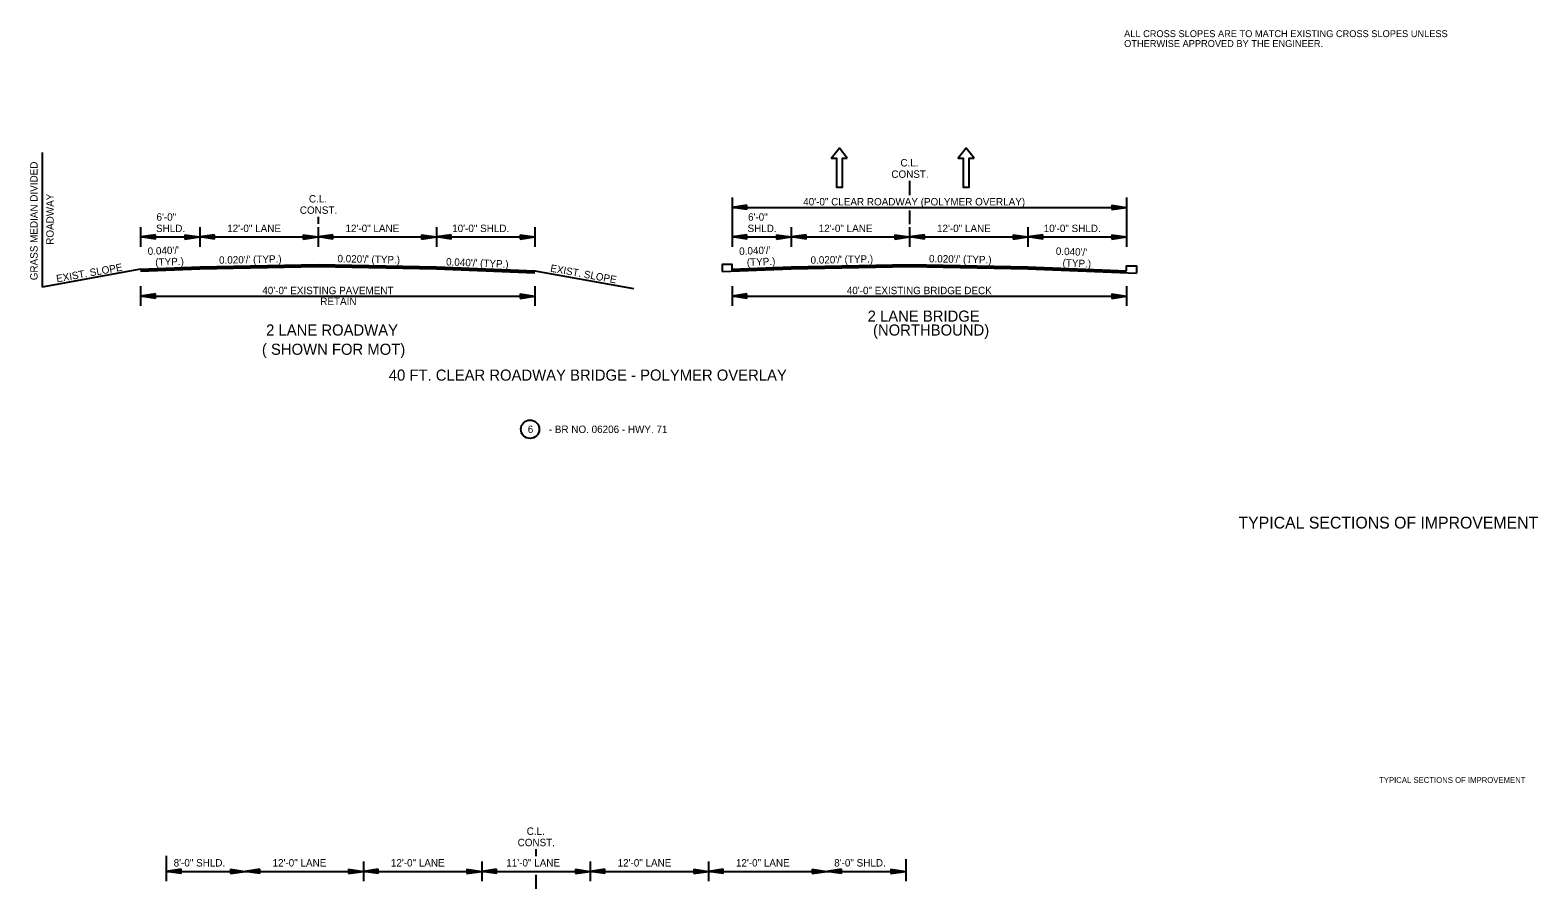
# Model space of a CAD drawing. Extents: x 550980 to 1930787, y -1972975 to 596640.
# Drawn here: x 551017 to 552546, y -1947048 to -1946177 of the extents above; entities that cross this region are included whole.
import ezdxf

# ---------------------------------------------------------------- set-up
doc = ezdxf.new("R2010")
doc.units = 0
for name, color, linetype in [('R_Border', 7, 'Continuous'), ('R_Border Notes', 7, 'Continuous'), ('R_Draft', 7, 'Continuous'), ('S_AREA_CALC', 7, 'Continuous')]:
    doc.layers.add(name, color=color, linetype=linetype)

# ---------------------------------------------------------------- blocks, each defined once
blk = doc.blocks.new('BPPOLY')
at = {"layer": 'R_Border'}
blk.add_circle((0, 0), 9.34, dxfattribs=at)
blk = doc.blocks.new('ARROW')
at = {"layer": 'R_Draft'}
for p, q in [((-2, 0.3), (0, 0)), ((-2, 0.3), (-2, -0.3)), ((-2, 0.25), (-0.334, 0)), ((-2, 0.199), (-0.678, 0)), ((-2, 0.149), (-1.011, 0)), ((-2, 0.097), (-1.35, 0)), ((-2, 0.047), (-1.684, 0)), ((-2, -0.3), (0, 0)), ((-2, -0.098), (-1.35, 0)), ((-2, -0.199), (-0.678, 0)), ((-2, -0.25), (-0.334, 0)), ((-2, -0.149), (-1.011, 0)), ((-2, -0.047), (-1.684, 0))]:
    blk.add_line(p, q, dxfattribs=at)

msp = doc.modelspace()

# ---------------------------------------------------------------- linework, layer by layer
at = {"layer": 'R_Border'}
for p, q in [((551028.7, -1946300.8), (551028.7, -1946437.2)), ((551908.7, -1946329.4), (551908.7, -1946343.9)), ((551728.7, -1946346.4), (551728.7, -1946396.4)), ((552128.7, -1946346.4), (552128.7, -1946396.4)), ((551728.7, -1946356.4), (552128.7, -1946356.4)), ((551908.7, -1946359.4), (551908.7, -1946373.4)), ((551128.7, -1946376.4), (551128.7, -1946396.4)), ((551188.7, -1946376.4), (551188.7, -1946396.4)), ((551308.7, -1946365.9), (551308.7, -1946373.2)), ((551308.7, -1946376.4), (551308.7, -1946396.4)), ((551428.7, -1946376.4), (551428.7, -1946396.4)), ((551528.7, -1946376.4), (551528.7, -1946396.4)), ((551788.7, -1946376.4), (551788.7, -1946396.4)), ((551908.7, -1946376.4), (551908.7, -1946396.4)), ((552028.7, -1946376.4), (552028.7, -1946396.4)), ((551128.7, -1946386.4), (551528.7, -1946386.4)), ((551728.7, -1946386.4), (552128.7, -1946386.4)), ((551128.7, -1946419.2), (551028.7, -1946437.2)), ((551528.7, -1946420.8), (551628.7, -1946438.8)), ((551128.7, -1946436.4), (551128.7, -1946456.4)), ((551528.7, -1946436.4), (551528.7, -1946456.4)), ((551728.7, -1946436.4), (551728.7, -1946456.4)), ((552128.7, -1946436.4), (552128.7, -1946456.4)), ((551128.7, -1946446.4), (551528.7, -1946446.4)), ((551728.7, -1946446.4), (552128.7, -1946446.4)), ((551154.7, -1947014), (551154.7, -1947039.9)), ((551529.7, -1947007.3), (551529.7, -1947014.5)), ((551904.7, -1947017.4), (551904.7, -1947039.9)), ((551154.7, -1947029.9), (551904.7, -1947029.9)), ((551354.7, -1947019.9), (551354.7, -1947039.9)), ((551474.7, -1947019.9), (551474.7, -1947039.9)), ((551529.7, -1947033.5), (551529.7, -1947047.5)), ((551584.7, -1947019.9), (551584.7, -1947039.9)), ((551704.7, -1947019.9), (551704.7, -1947039.9))]:
    msp.add_line(p, q, dxfattribs=at)
for points in [[(551845.5, -1946306.6), (551837.5, -1946296.2), (551829.5, -1946306.6), (551834.5, -1946306.6), (551834.5, -1946336), (551840.5, -1946336), (551840.5, -1946306.6)], [(551974.1, -1946306.6), (551966.1, -1946296.2), (551958.1, -1946306.6), (551963.1, -1946306.6), (551963.1, -1946336), (551969.1, -1946336), (551969.1, -1946306.6)]]:
    msp.add_lwpolyline(points, close=True, dxfattribs=at)
for points in [[(551128.7, -1946419.2), (551188.7, -1946416.8), (551308.7, -1946414.4), (551428.7, -1946416.8), (551528.7, -1946420.8)], [(551128.7, -1946419.5), (551188.7, -1946417.1), (551308.7, -1946414.7), (551428.7, -1946417.1), (551528.7, -1946421.1)], [(551128.7, -1946419.8), (551188.7, -1946417.4), (551308.7, -1946415), (551428.7, -1946417.4), (551528.7, -1946421.4)], [(551128.7, -1946420.1), (551188.7, -1946417.7), (551308.7, -1946415.3), (551428.7, -1946417.7), (551528.7, -1946421.7)], [(551128.7, -1946420.4), (551188.7, -1946418), (551308.7, -1946415.6), (551428.7, -1946418), (551528.7, -1946422)], [(551128.7, -1946420.7), (551188.7, -1946418.3), (551308.7, -1946415.9), (551428.7, -1946418.3), (551528.7, -1946422.3)], [(551128.7, -1946421), (551188.7, -1946418.6), (551308.7, -1946416.2), (551428.7, -1946418.6), (551528.7, -1946422.6)], [(551728.7, -1946420.7), (551728.7, -1946414.2), (551718.7, -1946414.2), (551718.7, -1946421.4)], [(551718.7, -1946421.4), (551788.7, -1946418.6), (551908.7, -1946416.2), (552028.7, -1946418.6), (552138.7, -1946423)], [(551728.7, -1946419.2), (551788.7, -1946416.8), (551908.7, -1946414.4), (552028.7, -1946416.8), (552128.7, -1946420.8)], [(551728.7, -1946419.5), (551788.7, -1946417.1), (551908.7, -1946414.7), (552028.7, -1946417.1), (552128.7, -1946421.1)], [(551728.7, -1946419.8), (551788.7, -1946417.4), (551908.7, -1946415), (552028.7, -1946417.4), (552128.7, -1946421.4)], [(551728.7, -1946420.1), (551788.7, -1946417.7), (551908.7, -1946415.3), (552028.7, -1946417.7), (552128.7, -1946421.7)], [(551728.7, -1946420.4), (551788.7, -1946418), (551908.7, -1946415.6), (552028.7, -1946418), (552128.7, -1946422)], [(551728.7, -1946420.7), (551788.7, -1946418.3), (551908.7, -1946415.9), (552028.7, -1946418.3), (552128.7, -1946422.3)], [(552128.7, -1946420.8), (552128.7, -1946415.8), (552138.7, -1946415.8), (552138.7, -1946423)]]:
    msp.add_lwpolyline(points, dxfattribs=at)

# ---------------------------------------------------------------- block references
at = {"layer": 'R_Border', "xscale": 7.5, "yscale": 7.5, "rotation": 180}
for p in [(551728.7, -1946356.4), (551128.7, -1946386.4), (551188.7, -1946386.4), (551308.7, -1946386.4), (551428.7, -1946386.4), (551728.7, -1946386.4), (551788.7, -1946386.4), (551908.7, -1946386.4), (552028.7, -1946386.4), (551128.7, -1946446.4), (551728.7, -1946446.4), (551154.7, -1947029.9), (551234.7, -1947029.9), (551354.7, -1947029.9), (551474.7, -1947029.9), (551584.7, -1947029.9), (551704.7, -1947029.9), (551824.7, -1947029.9)]:
    msp.add_blockref('ARROW', p, dxfattribs=at)
at = {"layer": 'R_Border', "xscale": 7.5, "yscale": 7.5}
for p in [(552128.7, -1946356.4), (551188.7, -1946386.4), (551308.7, -1946386.4), (551428.7, -1946386.4), (551528.7, -1946386.4), (551788.7, -1946386.4), (551908.7, -1946386.4), (552028.7, -1946386.4), (552128.7, -1946386.4), (551528.7, -1946446.4), (552128.7, -1946446.4), (551234.7, -1947029.9), (551354.7, -1947029.9), (551474.7, -1947029.9), (551584.7, -1947029.9), (551704.7, -1947029.9), (551824.7, -1947029.9), (551904.7, -1947029.9)]:
    msp.add_blockref('ARROW', p, dxfattribs=at)
at = {"layer": 'R_Border'}
msp.add_blockref('BPPOLY', (551523.7, -1946581.4), dxfattribs=at)

# ---------------------------------------------------------------- texts
for s, height, rotation, p in [('GRASS MEDIAN DIVIDED', 7.5, 90, (551024.2, -1946430.3)), ('ROADWAY', 7.5, 90, (551040.5, -1946394.3)), ("0.040'/'", 7.5, 2.2916, (551136, -1946404.6)), ('(TYP.)', 7.5, 2.2916, (551143.7, -1946415.8)), ("0.020'/' (TYP.)", 7.5, 1.1458, (551208.3, -1946413.6)), ("0.020'/' (TYP.)", 7.5, 358.8542, (551328.3, -1946412)), ("0.040'/' (TYP.)", 7.5, 357.7084, (551438.4, -1946415.2)), ("0.040'/'", 7.5, 2.2916, (551736, -1946404.6)), ('(TYP.)', 7.5, 2.2916, (551743.7, -1946415.8)), ("0.020'/' (TYP.)", 7.5, 1.1458, (551808.3, -1946413.6)), ("0.020'/' (TYP.)", 7.5, 358.8542, (551928.3, -1946412)), ("0.040'/'", 7.5, 357.7084, (552056.9, -1946404.4)), ('EXIST. SLOPE', 7.5, 10.204, (551043.8, -1946432.5)), ('EXIST. SLOPE', 7.5, 349.796, (551543.8, -1946421.5)), ('(TYP.)', 7.5, 357.7084, (552063.7, -1946416.2)), ('TYPICAL SECTIONS OF IMPROVEMENT', 12, 360, (552242.3, -1946682.1))]:
    msp.add_text(s, height=height, rotation=rotation, dxfattribs=at).set_placement(p)
for s, height, p in [('C.L.', 7.5, (551899.4, -1946314.9)), ('CONST.', 7.5, (551890.2, -1946326.4)), ('C.L.', 7.5, (551299.4, -1946351.4)), ('40\'-0" CLEAR ROADWAY (POLYMER OVERLAY)', 7.5, (551800.8, -1946354.4)), ('CONST.', 7.5, (551290.2, -1946362.9)), ('SHLD.', 7.5, (551144.3, -1946381.4)), ('6\'-0"', 7.5, (551144.8, -1946369.9)), ('12\'-0" LANE', 7.5, (551216.5, -1946381.4)), ('12\'-0" LANE', 7.5, (551336.5, -1946381.4)), ('10\'-0" SHLD.', 7.5, (551444.7, -1946381.4)), ('SHLD.', 7.5, (551744.3, -1946381.4)), ('6\'-0"', 7.5, (551744.8, -1946369.9)), ('12\'-0" LANE', 7.5, (551816.5, -1946381.4)), ('12\'-0" LANE', 7.5, (551936.5, -1946381.4)), ('10\'-0" SHLD.', 7.5, (552044.7, -1946381.4)), ('40\'-0" EXISTING PAVEMENT', 7.5, (551252.1, -1946444.4)), ('40\'-0" EXISTING BRIDGE DECK', 7.5, (551845, -1946444.4)), ('RETAIN', 7.5, (551310.9, -1946455.4)), ('2 LANE BRIDGE', 11.25, (551866.1, -1946472.3)), ('2 LANE ROADWAY', 11.25, (551256, -1946486.4)), ('(NORTHBOUND)', 11.25, (551871.6, -1946486.4)), ('( SHOWN FOR MOT)', 11.25, (551251.7, -1946505.9)), ('40 FT. CLEAR ROADWAY BRIDGE - POLYMER OVERLAY', 11.25, (551380.4, -1946532.1)), ('6', 7.5, (551521.4, -1946585.2)), ('- BR NO. 06206 - HWY. 71', 7.5, (551542.7, -1946585.2)), ('C.L.', 7.5, (551520.3, -1946992.8)), ('CONST.', 7.5, (551511.1, -1947004.3)), ('8\'-0" SHLD.', 7.5, (551162.2, -1947024.9)), ('12\'-0" LANE', 7.5, (551262.5, -1947024.9)), ('12\'-0" LANE', 7.5, (551382.5, -1947024.9)), ('11\'-0" LANE', 7.5, (551499.6, -1947024.9)), ('12\'-0" LANE', 7.5, (551612.5, -1947024.9)), ('12\'-0" LANE', 7.5, (551732.5, -1947024.9)), ('8\'-0" SHLD.', 7.5, (551832.2, -1947024.9))]:
    msp.add_text(s, height=height, dxfattribs=at).set_placement(p)
at = {"layer": 'R_Border Notes'}
for s, p in [('ALL CROSS SLOPES ARE TO MATCH EXISTING CROSS SLOPES UNLESS ', (552126.3, -1946183.7)), ('OTHERWISE APPROVED BY THE ENGINEER.', (552126.3, -1946193.7))]:
    msp.add_text(s, height=7, dxfattribs=at).set_placement(p)
at = {"layer": 'S_AREA_CALC'}
msp.add_text('TYPICAL SECTIONS OF IMPROVEMENT', height=5.862, rotation=360, dxfattribs=at).set_placement((552384.9, -1946940.1))

doc.saveas('drawing.dxf')
